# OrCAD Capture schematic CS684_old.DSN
size A
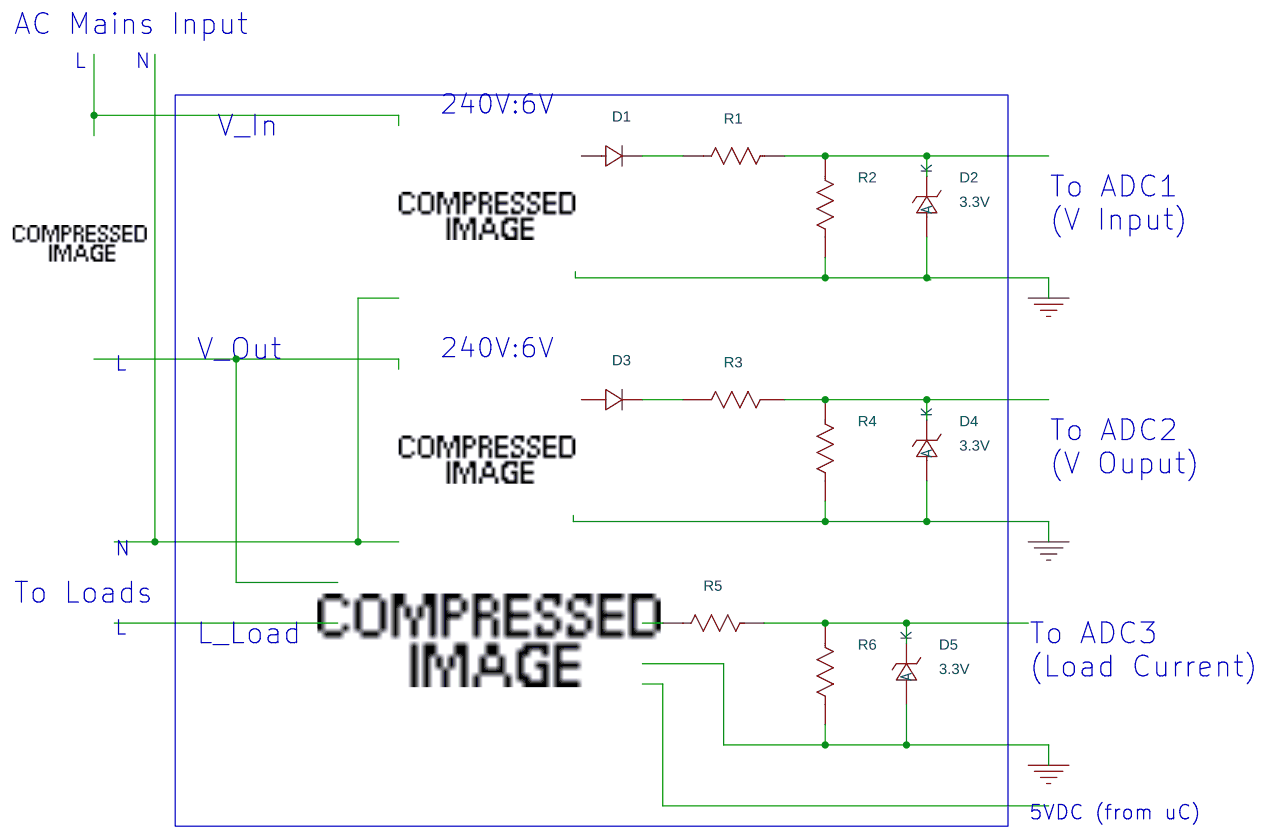
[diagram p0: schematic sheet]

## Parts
D1  d
D2  3.3V  [DO-7]
D3  d
D4  3.3V  [DO-7]
D5  3.3V  [DO-7]
R1  10k
R2  10k
R3  10k
R4  10k
R5  1.7k
R6  3.3k

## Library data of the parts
D1 D3 = d
D2 D4 D5 = 1N4099
R1-R6 = RESISTOR

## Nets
GND: D2.1(A) D4.1(A) D5.1(A) R2.1(A) R4.1(A) R6.1(A)
N00103: D1.1(2) R1.1(A)
N00107: D2.2(K) R1.2(B) R2.2(B)
N00771: D3.1(2) R3.1(A)
N00775: D4.2(K) R3.2(B) R4.2(B)
N01433: D5.2(K) R5.2(B) R6.2(B)

Not connected (* = marked no-connect by the designer): D1 0(1); D3 0(1); R5 1(A)

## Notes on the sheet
- AC Mains Input
- L
- N
- 240V:6V
- V_In
- To ADC1
  (V Input)
- L
- V_Out
- 240V:6V
- To ADC2
  (V Ouput)
- N
- To Loads
- L
- L_Load
- To ADC3
  (Load Current)
- 5VDC (from uC)
